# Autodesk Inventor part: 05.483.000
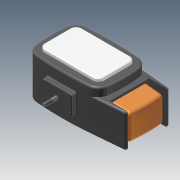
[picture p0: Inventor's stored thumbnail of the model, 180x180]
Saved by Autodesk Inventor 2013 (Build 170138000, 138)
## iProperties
Created: 2005-07
Part Number: 05.483.000
Material: Steel, Mild
Document SubType Name: Modeling
Designer: PVitaliy
Manufacturer: Standard
Standards Organization: Custom
Density: 7.86 g/cm^3
Author: PVitaliy
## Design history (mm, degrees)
derived "05.479.000.ipt"
body "Solid1"
tag "TaggingFeature2"
feature "Solid1::05.479.000.ipt" dims "d3" = 10
